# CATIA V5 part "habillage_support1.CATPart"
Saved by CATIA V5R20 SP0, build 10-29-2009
Part number: habillage_support1
Bounding box of the stored display mesh (mm): x 100 to 110, y -360 to 60, z -10 to 10
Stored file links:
  C:\Users\Noëllie\Documents\IFMA\2A\S3\IAO\Projet Artobolevski\Catia\habillage_support1.CATPart
  C:\Users\Noëllie\Documents\IFMA\2A\S3\IAO\Projet Artobolevski\Catia\assemblage_balance.CATProduct
  C:\Users\Noëllie\Documents\IFMA\2A\S3\IAO\Projet Artobolevski\Catia\habillage_base.CATPart
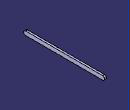
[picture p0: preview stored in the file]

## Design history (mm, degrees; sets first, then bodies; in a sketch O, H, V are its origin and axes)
Parameters
  h = 20 mm
  b = 10 mm
Set1
  Plane1 "Plan_base1": linked copy from another document
  Point1 "B1g": linked copy from another document
  Point2 "B1d": linked copy from another document
Body1 (main body)
  Sketch1 on Plane1, origin (100, 0, 0), H (0, 1, 0), V (0, 0, 1)
    line L1 (-350, 10) -> (50, 10)
    line L2 (-350, -10) -> (50, -10)
    arc A1 centre (50, 0) radius 10 from (50, 10) to (50, -10) cw
    point P5 (50, 0)
    arc A2 centre (-350, 0) radius 10 from (-350, 10) to (-350, -10) ccw
    point P6 (-350, 0)
    point P7 (-360, 0)
    reference projected point E1 (-350, 0) from Point1
    reference projected point E2 (50, 0) from Point2
    length L2 = 400
    distance L1 L2 = 20 {= h}
    horizontal: L1 H, L2 H
    tangency: A1 L2, A2 L1
    coincidence: A2 P7, P7 H, P6 E1, P5 E2
  Pad1: profile Sketch1, direction (1, 0, 0), length 10 {= b}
